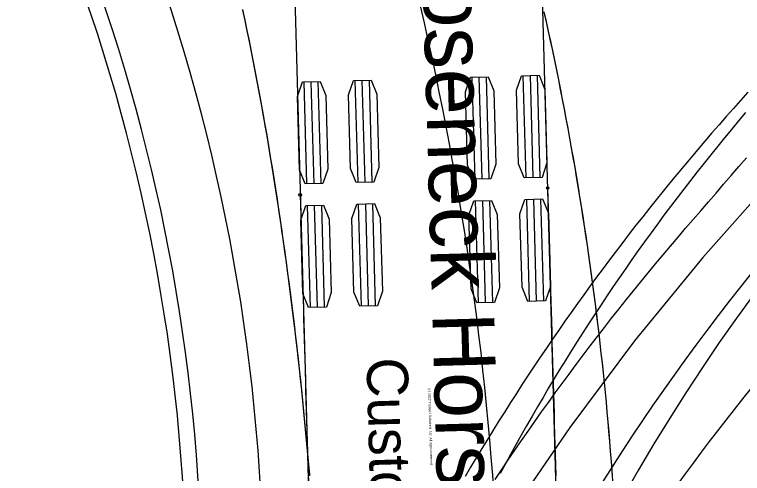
# Model space of a CAD drawing. Extents: x -14 to 1565148, y -25 to 642856.
# Drawn here: x 1564752.48 to 1564776, y 636528.46 to 636543.3 of the extents above; entities that cross this region are included whole.
import ezdxf

# ---------------------------------------------------------------- set-up
doc = ezdxf.new("R2010")
doc.units = 0
for name, color, linetype in [('DR_P_Headwall', 7, 'Continuous'), ('GE_P_Alignment_100_Stations', 7, 'Continuous'), ('GE_P_Driveway_CL', 7, 'Continuous'), ('GE_X_Alignment', 7, 'Continuous'), ('PV_P_EOP', 7, 'Continuous'), ('PV_X_EOP', 7, 'Continuous'), ('TR_Turning_Path22', 7, 'Continuous'), ('TR_Turning_Path28', 7, 'Continuous'), ('TR_Turning_Path28 - Copy-1', 7, 'Continuous')]:
    doc.layers.add(name, color=color, linetype=linetype)

msp = doc.modelspace()

# ---------------------------------------------------------------- linework, layer by layer
at = {"layer": 'DR_P_Headwall'}
for points in [[(1564762.014, 636528.408), (1564761.984, 636528.752), (1564761.954, 636529.096), (1564761.922, 636529.44), (1564761.89, 636529.785), (1564761.858, 636530.129), (1564761.824, 636530.473), (1564761.789, 636530.817), (1564761.754, 636531.162), (1564761.718, 636531.506), (1564761.681, 636531.85), (1564761.643, 636532.194), (1564761.604, 636532.538), (1564761.564, 636532.882), (1564761.524, 636533.226), (1564761.482, 636533.57), (1564761.44, 636533.914), (1564761.397, 636534.258), (1564761.352, 636534.601), (1564761.307, 636534.945), (1564761.261, 636535.288), (1564761.214, 636535.631), (1564761.166, 636535.974), (1564761.117, 636536.317), (1564761.068, 636536.659), (1564761.017, 636537.002), (1564760.965, 636537.344), (1564760.912, 636537.686), (1564760.858, 636538.028), (1564760.804, 636538.369), (1564760.748, 636538.711), (1564760.691, 636539.052), (1564760.633, 636539.392), (1564760.574, 636539.733), (1564760.514, 636540.073), (1564760.453, 636540.413), (1564760.391, 636540.752), (1564760.327, 636541.091), (1564760.263, 636541.43), (1564760.197, 636541.769), (1564760.131, 636542.107), (1564760.063, 636542.445), (1564759.994, 636542.782), (1564759.924, 636543.119), (1564759.853, 636543.456)], [(1564762.016, 636528.381), (1564761.987, 636528.725), (1564761.956, 636529.07), (1564761.925, 636529.414), (1564761.893, 636529.758), (1564761.86, 636530.103), (1564761.827, 636530.447), (1564761.792, 636530.792), (1564761.757, 636531.136), (1564761.721, 636531.48), (1564761.684, 636531.825), (1564761.646, 636532.169), (1564761.607, 636532.513), (1564761.567, 636532.857), (1564761.527, 636533.202), (1564761.485, 636533.546), (1564761.443, 636533.89), (1564761.4, 636534.233), (1564761.356, 636534.577), (1564761.311, 636534.921), (1564761.265, 636535.265), (1564761.218, 636535.608), (1564761.17, 636535.951), (1564761.121, 636536.294), (1564761.071, 636536.637), (1564761.02, 636536.98), (1564760.968, 636537.322), (1564760.916, 636537.665), (1564760.862, 636538.007), (1564760.807, 636538.349), (1564760.751, 636538.69), (1564760.694, 636539.032), (1564760.636, 636539.373), (1564760.577, 636539.714), (1564760.517, 636540.054), (1564760.456, 636540.394), (1564760.394, 636540.734), (1564760.331, 636541.074), (1564760.266, 636541.413), (1564760.201, 636541.752), (1564760.134, 636542.091), (1564760.066, 636542.429), (1564759.997, 636542.767), (1564759.927, 636543.104), (1564759.856, 636543.441)], [(1564769.581, 636543.386), (1564769.65, 636543.073), (1564769.719, 636542.759), (1564769.787, 636542.446), (1564769.853, 636542.132), (1564769.919, 636541.819), (1564769.983, 636541.505), (1564770.047, 636541.191), (1564770.11, 636540.877), (1564770.171, 636540.562), (1564770.232, 636540.248), (1564770.292, 636539.933), (1564770.35, 636539.619), (1564770.408, 636539.304), (1564770.464, 636538.989), (1564770.52, 636538.674), (1564770.575, 636538.359), (1564770.628, 636538.044), (1564770.681, 636537.728), (1564770.732, 636537.413), (1564770.783, 636537.097), (1564770.833, 636536.782), (1564770.881, 636536.466), (1564770.929, 636536.15), (1564770.976, 636535.834), (1564771.021, 636535.518), (1564771.066, 636535.202), (1564771.11, 636534.886), (1564771.152, 636534.569), (1564771.194, 636534.253), (1564771.235, 636533.936), (1564771.274, 636533.62), (1564771.313, 636533.303), (1564771.351, 636532.986), (1564771.387, 636532.669), (1564771.423, 636532.352), (1564771.458, 636532.035), (1564771.492, 636531.718), (1564771.524, 636531.401), (1564771.556, 636531.084), (1564771.587, 636530.766), (1564771.617, 636530.448), (1564771.646, 636530.131), (1564771.673, 636529.813), (1564771.7, 636529.495), (1564771.726, 636529.176), (1564771.751, 636528.858), (1564771.775, 636528.54), (1564771.797, 636528.221)], [(1564769.583, 636543.378), (1564769.652, 636543.065), (1564769.721, 636542.751), (1564769.789, 636542.438), (1564769.855, 636542.124), (1564769.921, 636541.81), (1564769.985, 636541.496), (1564770.049, 636541.182), (1564770.112, 636540.868), (1564770.173, 636540.553), (1564770.234, 636540.239), (1564770.294, 636539.924), (1564770.352, 636539.609), (1564770.41, 636539.295), (1564770.466, 636538.98), (1564770.522, 636538.665), (1564770.576, 636538.349), (1564770.63, 636538.034), (1564770.683, 636537.719), (1564770.734, 636537.403), (1564770.785, 636537.088), (1564770.834, 636536.772), (1564770.883, 636536.457), (1564770.931, 636536.141), (1564770.977, 636535.825), (1564771.023, 636535.509), (1564771.067, 636535.193), (1564771.111, 636534.877), (1564771.154, 636534.561), (1564771.195, 636534.244), (1564771.236, 636533.928), (1564771.275, 636533.612), (1564771.314, 636533.295), (1564771.352, 636532.978), (1564771.388, 636532.662), (1564771.424, 636532.345), (1564771.459, 636532.028), (1564771.493, 636531.711), (1564771.525, 636531.394), (1564771.557, 636531.076), (1564771.588, 636530.759), (1564771.617, 636530.441), (1564771.646, 636530.124), (1564771.674, 636529.806), (1564771.701, 636529.488), (1564771.726, 636529.17), (1564771.751, 636528.852), (1564771.775, 636528.533), (1564771.798, 636528.215)]]:
    msp.add_lwpolyline(points, dxfattribs=at)
msp.add_arc((1564669.832, 636521.078), 98.366, 354.31091, 15.55333, dxfattribs=at)
at = {"layer": 'GE_P_Alignment_100_Stations'}
for points in [[(1564778.458, 636539.56), (1564777.033, 636538.052), (1564774.712, 636535.446), (1564772.505, 636532.742), (1564770.416, 636529.946), (1564768.451, 636527.062), (1564766.612, 636524.095), (1564764.902, 636521.052), (1564763.325, 636517.938), (1564761.885, 636514.759)], [(1564768.006, 636528.265), (1564768.216, 636528.58), (1564768.428, 636528.894), (1564768.641, 636529.207), (1564768.855, 636529.519), (1564769.071, 636529.83), (1564769.288, 636530.139), (1564769.507, 636530.448), (1564769.727, 636530.756), (1564769.949, 636531.063), (1564770.172, 636531.368), (1564770.396, 636531.673), (1564770.622, 636531.977), (1564770.849, 636532.279), (1564771.077, 636532.581), (1564771.307, 636532.881), (1564771.538, 636533.179), (1564771.769, 636533.476), (1564772.002, 636533.772), (1564772.237, 636534.067), (1564772.473, 636534.36), (1564772.71, 636534.653), (1564772.948, 636534.945), (1564773.188, 636535.235), (1564773.429, 636535.524), (1564773.671, 636535.812), (1564773.915, 636536.099), (1564774.16, 636536.385), (1564774.406, 636536.67), (1564774.654, 636536.954), (1564774.901, 636537.238), (1564775.145, 636537.524), (1564775.389, 636537.811), (1564775.634, 636538.097), (1564775.88, 636538.383), (1564776.127, 636538.667)]]:
    msp.add_lwpolyline(points, dxfattribs=at)
msp.add_arc((1564836.199, 636482.996), 76.916, 136.63219, 157.42198, dxfattribs=at)
at = {"layer": 'GE_P_Driveway_CL'}
msp.add_arc((1564834.986, 636485.101), 60.333, 360, 269.30622, dxfattribs=at)
msp.add_arc((1564834.986, 636485.101), 60.333, 360, 269.30622, dxfattribs=at)
at = {"layer": 'GE_X_Alignment'}
msp.add_circle((1564834.986, 636485.101), 60.25, dxfattribs=at)
at = {"layer": 'PV_P_EOP'}
for radius in [62, 60.333, 60.25]:
    msp.add_circle((1564834.986, 636485.101), radius, dxfattribs=at)
for radius in [60, 59.5]:
    msp.add_arc((1564698.532, 636524.398), radius, 343.93404, 24.95884, dxfattribs=at)
at = {"layer": 'PV_X_EOP'}
msp.add_arc((1564698.532, 636524.398), 62, 343.93404, 24.95884, dxfattribs=at)
at = {"layer": 'TR_Turning_Path22'}
for p, q in [((1564770.426, 636511.698), (1564769.424, 636547.684)), ((1564761.427, 636547.461), (1564762.429, 636511.475)), ((1564767.356, 636537.973), (1564767.264, 636541.271)), ((1564767.585, 636537.979), (1564767.493, 636541.278)), ((1564767.814, 636537.985), (1564767.722, 636541.284)), ((1564769.005, 636538.019), (1564768.913, 636541.317)), ((1564769.234, 636538.025), (1564769.142, 636541.324)), ((1564769.463, 636538.031), (1564769.371, 636541.33)), ((1564761.925, 636537.821), (1564761.833, 636541.12)), ((1564762.154, 636537.828), (1564762.062, 636541.126)), ((1564762.383, 636537.834), (1564762.291, 636541.133)), ((1564763.574, 636537.867), (1564763.482, 636541.166)), ((1564763.803, 636537.874), (1564763.711, 636541.172)), ((1564764.032, 636537.88), (1564763.94, 636541.179)), ((1564767.467, 636533.974), (1564767.375, 636537.273)), ((1564767.696, 636533.981), (1564767.604, 636537.279)), ((1564767.925, 636533.987), (1564767.833, 636537.286)), ((1564769.116, 636534.02), (1564769.025, 636537.319)), ((1564769.346, 636534.026), (1564769.254, 636537.325)), ((1564769.575, 636534.033), (1564769.483, 636537.332)), ((1564762.036, 636533.823), (1564761.944, 636537.122)), ((1564762.265, 636533.829), (1564762.173, 636537.128)), ((1564762.494, 636533.836), (1564762.402, 636537.134)), ((1564763.685, 636533.869), (1564763.593, 636537.168)), ((1564763.914, 636533.875), (1564763.822, 636537.174)), ((1564764.143, 636533.882), (1564764.052, 636537.18))]:
    msp.add_line(p, q, dxfattribs=at)
for points in [[(1564764.089, 636537.882), (1564763.517, 636537.866), (1564763.332, 636538.323), (1564763.266, 636540.698), (1564763.425, 636541.164), (1564763.997, 636541.18), (1564764.182, 636540.723), (1564764.248, 636538.348)], [(1564767.871, 636537.987), (1564767.299, 636537.971), (1564767.114, 636538.428), (1564767.048, 636540.803), (1564767.207, 636541.27), (1564767.779, 636541.286), (1564767.964, 636540.829), (1564768.03, 636538.454)], [(1564769.52, 636538.033), (1564768.948, 636538.017), (1564768.763, 636538.474), (1564768.697, 636540.849), (1564768.856, 636541.316), (1564769.428, 636541.332), (1564769.613, 636540.875), (1564769.679, 636538.5)], [(1564762.44, 636537.836), (1564761.868, 636537.82), (1564761.683, 636538.277), (1564761.616, 636540.652), (1564761.776, 636541.119), (1564762.348, 636541.134), (1564762.533, 636540.677), (1564762.599, 636538.302)], [(1564767.982, 636533.989), (1564767.41, 636533.973), (1564767.225, 636534.43), (1564767.159, 636536.805), (1564767.318, 636537.271), (1564767.89, 636537.287), (1564768.075, 636536.83), (1564768.141, 636534.455)], [(1564769.631, 636534.034), (1564769.06, 636534.019), (1564768.875, 636534.476), (1564768.808, 636536.851), (1564768.968, 636537.317), (1564769.54, 636537.333), (1564769.725, 636536.876), (1564769.791, 636534.501)], [(1564762.551, 636533.837), (1564761.979, 636533.821), (1564761.794, 636534.278), (1564761.728, 636536.653), (1564761.887, 636537.12), (1564762.459, 636537.136), (1564762.644, 636536.679), (1564762.71, 636534.304)], [(1564764.2, 636533.883), (1564763.628, 636533.867), (1564763.443, 636534.324), (1564763.377, 636536.699), (1564763.537, 636537.166), (1564764.108, 636537.182), (1564764.293, 636536.725), (1564764.36, 636534.35)]]:
    msp.add_lwpolyline(points, close=True, dxfattribs=at)
for points in [[(1564769.702, 636537.688), (1564769.711, 636537.355), (1564769.721, 636537.021), (1564769.73, 636536.689), (1564769.739, 636536.357), (1564769.748, 636536.025), (1564769.758, 636535.693), (1564769.767, 636535.361), (1564769.776, 636535.029), (1564769.786, 636534.697), (1564769.795, 636534.365), (1564769.804, 636534.033), (1564769.813, 636533.701), (1564769.823, 636533.37), (1564769.832, 636533.038), (1564769.841, 636532.706), (1564769.851, 636532.374), (1564769.86, 636532.042), (1564769.87, 636531.71), (1564769.879, 636531.378), (1564769.889, 636531.047), (1564769.898, 636530.715), (1564769.908, 636530.383), (1564769.917, 636530.051), (1564769.927, 636529.719), (1564769.936, 636529.388), (1564769.946, 636529.056), (1564769.956, 636528.724), (1564769.965, 636528.392)], [(1564761.705, 636537.465), (1564761.714, 636537.132), (1564761.724, 636536.799), (1564761.733, 636536.467), (1564761.742, 636536.134), (1564761.752, 636535.802), (1564761.761, 636535.47), (1564761.77, 636535.138), (1564761.779, 636534.806), (1564761.789, 636534.474), (1564761.798, 636534.141), (1564761.807, 636533.809), (1564761.817, 636533.477), (1564761.826, 636533.145), (1564761.835, 636532.812), (1564761.845, 636532.48), (1564761.854, 636532.148), (1564761.863, 636531.815), (1564761.873, 636531.483), (1564761.882, 636531.151), (1564761.892, 636530.818), (1564761.901, 636530.486), (1564761.911, 636530.154), (1564761.92, 636529.821), (1564761.93, 636529.489), (1564761.94, 636529.157), (1564761.949, 636528.824), (1564761.959, 636528.492), (1564761.969, 636528.159)]]:
    msp.add_lwpolyline(points, dxfattribs=at)
for centre in [(1564769.702, 636537.688), (1564761.705, 636537.465)]:
    msp.add_circle(centre, 0.0417, dxfattribs=at)
at = {"layer": 'TR_Turning_Path28'}
msp.add_lwpolyline([(1564776.173, 636540.782), (1564775.938, 636540.521), (1564775.703, 636540.259), (1564775.47, 636539.997), (1564775.239, 636539.733), (1564775.008, 636539.468), (1564774.779, 636539.202), (1564774.551, 636538.935), (1564774.324, 636538.666), (1564774.098, 636538.397), (1564773.874, 636538.127), (1564773.651, 636537.856), (1564773.429, 636537.583), (1564773.209, 636537.31), (1564772.99, 636537.035), (1564772.772, 636536.76), (1564772.555, 636536.484), (1564772.34, 636536.206), (1564772.126, 636535.928), (1564771.913, 636535.648), (1564771.702, 636535.368), (1564771.492, 636535.086), (1564771.283, 636534.804), (1564771.076, 636534.52), (1564770.869, 636534.236), (1564770.665, 636533.951), (1564770.461, 636533.664), (1564770.259, 636533.377), (1564770.058, 636533.089), (1564769.859, 636532.8), (1564769.661, 636532.51), (1564769.464, 636532.219), (1564769.269, 636531.927), (1564769.075, 636531.634), (1564768.882, 636531.34), (1564768.691, 636531.045), (1564768.501, 636530.75), (1564768.313, 636530.454), (1564768.126, 636530.156), (1564767.94, 636529.858), (1564767.756, 636529.559), (1564767.573, 636529.259), (1564767.392, 636528.958), (1564767.212, 636528.657), (1564767.033, 636528.354)], dxfattribs=at)
msp.add_arc((1564831.717, 636490.351), 71.137, 131.98004, 162.83063, dxfattribs=at)
at = {"layer": 'TR_Turning_Path28 - Copy-1'}
msp.add_lwpolyline([(1564776.1, 636540.127), (1564775.872, 636539.857), (1564775.645, 636539.585), (1564775.42, 636539.313), (1564775.197, 636539.039), (1564774.975, 636538.764), (1564774.754, 636538.488), (1564774.535, 636538.21), (1564774.317, 636537.932), (1564774.101, 636537.652), (1564773.886, 636537.371), (1564773.673, 636537.089), (1564773.461, 636536.806), (1564773.251, 636536.522), (1564773.042, 636536.237), (1564772.835, 636535.95), (1564772.63, 636535.662), (1564772.426, 636535.374), (1564772.223, 636535.084), (1564772.022, 636534.793), (1564771.823, 636534.501), (1564771.625, 636534.208), (1564771.428, 636533.914), (1564771.234, 636533.619), (1564771.041, 636533.323), (1564770.849, 636533.026), (1564770.659, 636532.728), (1564770.471, 636532.429), (1564770.284, 636532.129), (1564770.099, 636531.827), (1564769.915, 636531.525), (1564769.733, 636531.222), (1564769.553, 636530.918), (1564769.374, 636530.613), (1564769.197, 636530.307), (1564769.022, 636530), (1564768.848, 636529.692), (1564768.676, 636529.384), (1564768.505, 636529.074), (1564768.336, 636528.763), (1564768.169, 636528.452)], dxfattribs=at)
msp.add_arc((1564826.601, 636497.291), 62.371, 105.98192, 163.48735, dxfattribs=at)

# ---------------------------------------------------------------- texts
at = {"layer": 'TR_Turning_Path22'}
for s, height, p in [('Gooseneck Horse Trailer', 2, (1564765.576, 636547.91)), ('Custom', 1.3333, (1564763.846, 636532.189)), ('(c) 2022 Transoft Solutions, Inc. All rights reserved.', 0.08, (1564765.841, 636531.216))]:
    msp.add_text(s, height=height, rotation=271.5952, dxfattribs=at).set_placement(p)

doc.saveas('drawing.dxf')
